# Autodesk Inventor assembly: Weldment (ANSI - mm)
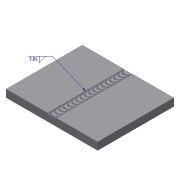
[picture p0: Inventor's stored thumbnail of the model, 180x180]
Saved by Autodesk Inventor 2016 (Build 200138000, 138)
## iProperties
Length Units: 11269
Angle Units: 11283
Time Units: 11279
Mass Units: 11290
Length Display Precision: 3
Angle Display Precision: 2
Part Number: Weldment (ANSI - mm)
Document SubType Name: Weldment
Created: 2002-06
Designer: smithga
Part Number: fig 16-6
Created: 2003-01
Designer: Owner
Control State: 0
Master: False
Shininess: 64.0
Angle Units: 11279
Time Units: 11290
Mass Units: 11283
Compacted: True
Density: 0.0
Volumn: 0.0
Area: 0.0
PropertySet Name: Model Information
Author: Owner
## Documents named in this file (2)
- D:\KAVITA\Autodesk Inventor_ 2016 Project_Kavita\Inventor_Part Files\Inventor_2016_Part\c16_Inv_2016\c16_inv_2016_prt\fig 16-6\fig 16-6.iam
- D:\KAVITA\Autodesk Inventor_ 2016 Project_Kavita\Inventor_Part Files\Inventor_2016_Part\c16_Inv_2016\c16_inv_2016_prt\fig 16-6\Part1.ipt
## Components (2 placed, 1 different names)
1. Part1:1 — Mate:1, Flush:1, Flush:2
2. Part1:2 — Mate:1, Flush:1, Flush:2
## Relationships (3: Flush 2, Mate 1)
- Mate:1: Part1:1 ↔ Part1:2
- Flush:1: Part1:1 ↔ Part1:2
- Flush:2: Part1:1 ↔ Part1:2
